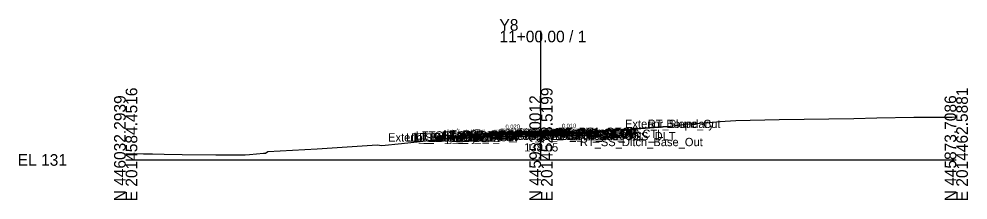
# Model space of a CAD drawing. Extents: x -26 to 1403, y -10 to 8043.
# Drawn here: x -25.7 to 202.8, y 1990.3 to 2034.1 of the extents above; entities that cross this region are included whole.
import ezdxf

# ---------------------------------------------------------------- set-up
doc = ezdxf.new("R2010")
doc.units = 0
for name, color, linetype in [('Default', 7, 'Continuous'), ('Exist CMT Pavement', 7, 'Continuous'), ('Exist Cross Section Cell', 7, 'Continuous'), ('Exist XS Center Line Elevation Label', 7, 'Continuous'), ('Exist XS Ground Line', 7, 'Continuous'), ('Prop CMT Pvmt Course 1', 7, 'Continuous'), ('Prop CMT Pvmt Course 2', 7, 'Continuous'), ('Prop CMT Pvmt Course 3', 7, 'Continuous'), ('Prop CMT Pvmt Surface', 7, 'Continuous'), ('Prop CMT Pvmt Surface Shoulder', 7, 'Continuous'), ('Prop CMT Shld Paved Course 1', 7, 'Continuous'), ('Prop CMT Shld Paved Course 2', 7, 'Continuous'), ('Prop CMT Shld Paved Course 3', 7, 'Continuous'), ('Prop CMT Slope Grass', 7, 'Continuous'), ('Prop CMT Subgrade Earthwork', 7, 'Continuous'), ('Prop XS Earthwork Shape', 7, 'Continuous'), ('Prop XS SE Text', 7, 'Continuous'), ('Prop XS Side Slope Text', 7, 'Continuous'), ('Scratch_Level_0', 7, 'Continuous')]:
    doc.layers.add(name, color=color, linetype=linetype)

msp = doc.modelspace()

# ---------------------------------------------------------------- linework, layer by layer
at = {"layer": 'Exist CMT Pavement'}
msp.add_lwpolyline([(88.73, 2006.68), (89.55, 2006.69), (99.48, 2007.03), (100, 2007.05), (100.46, 2007.07), (101.34, 2007.05), (111.48, 2006.77)], dxfattribs=at)
at = {"layer": 'Exist Cross Section Cell'}
for p, q in [((100, 2000), (100, 2031.22)), ((0, 2000), (100, 2000)), ((100, 2000), (200, 2000))]:
    msp.add_line(p, q, dxfattribs=at)
at = {"layer": 'Exist XS Ground Line'}
msp.add_lwpolyline([(0, 2001.54), (4.31, 2001.49), (6.46, 2001.47), (9.25, 2001.41), (13.59, 2001.31), (21.74, 2001.23), (28.74, 2001.22), (29.85, 2001.3), (33.17, 2001.63), (33.66, 2001.66), (34.23, 2002.08), (46.13, 2002.7), (60.54, 2003.65), (61.7, 2003.51), (66.38, 2004.01), (70.9, 2004.47), (83.32, 2005.96), (83.87, 2006.09), (88.73, 2006.68), (89.55, 2006.69), (99.48, 2007.03), (100, 2007.05), (100.46, 2007.07), (101.34, 2007.05), (111.48, 2006.77), (113.38, 2006.92), (118.89, 2007.28), (130.44, 2008.1), (134.84, 2008.61), (140.56, 2009.07), (143.05, 2009.26), (146.92, 2009.52), (157.35, 2009.8), (175.34, 2010.05), (180.89, 2010.18), (189.8, 2010.32), (193.51, 2010.33), (199.03, 2010.33), (200, 2010.41)], dxfattribs=at)
at = {"layer": 'Prop CMT Pvmt Course 1'}
for points in [[(100, 2006.68), (86.49, 2006.41)], [(100, 2006.68), (113.35, 2006.81)], [(100, 2006.43), (100, 2006.68)], [(100, 2006.43), (100, 2006.68)], [(113.35, 2006.56), (100, 2006.43)], [(113.35, 2006.81), (113.35, 2006.56)], [(86.49, 2006.16), (100, 2006.43)], [(86.49, 2006.41), (86.49, 2006.16)]]:
    msp.add_lwpolyline(points, dxfattribs=at)
msp.add_lwpolyline([(100, 2006.43), (100, 2006.56), (100, 2006.56), (100, 2006.43)], close=True, dxfattribs=at)
msp.add_lwpolyline([(100, 2006.43), (100, 2006.56), (100, 2006.56), (100, 2006.43)], close=True, dxfattribs=at)
at = {"layer": 'Prop CMT Pvmt Course 2'}
for points in [[(100, 2006.43), (113.35, 2006.56)], [(113.35, 2006.56), (113.35, 2006.31)], [(100, 2006.43), (86.49, 2006.16)], [(86.49, 2005.91), (100, 2006.18)], [(86.49, 2006.16), (86.49, 2005.91)], [(100, 2006.18), (100, 2006.43)], [(100, 2006.18), (100, 2006.43)], [(113.35, 2006.31), (100, 2006.18)]]:
    msp.add_lwpolyline(points, dxfattribs=at)
at = {"layer": 'Prop CMT Pvmt Course 3'}
for points in [[(100, 2006.18), (86.49, 2005.91)], [(86.49, 2005.91), (86.49, 2005.54)], [(86.49, 2005.54), (100, 2005.81)], [(100, 2006.18), (113.35, 2006.31)], [(100, 2005.81), (100, 2006.18)], [(100, 2005.81), (100, 2006.18)], [(113.35, 2005.94), (100, 2005.81)], [(113.35, 2006.31), (113.35, 2005.94)]]:
    msp.add_lwpolyline(points, dxfattribs=at)
at = {"layer": 'Prop CMT Pvmt Surface'}
for points in [[(100, 2006.68), (86.49, 2006.41)], [(100, 2006.68), (113.35, 2006.81)]]:
    msp.add_lwpolyline(points, dxfattribs=at)
at = {"layer": 'Prop CMT Pvmt Surface Shoulder'}
for points in [[(113.35, 2006.81), (113.35, 2006.81)], [(86.49, 2006.41), (86.49, 2006.41)]]:
    msp.add_lwpolyline(points, dxfattribs=at)
at = {"layer": 'Prop CMT Shld Paved Course 1'}
for points in [[(113.35, 2006.81), (113.35, 2006.81)], [(113.35, 2006.81), (113.6, 2006.56)], [(113.35, 2006.56), (113.35, 2006.81)], [(113.6, 2006.56), (113.35, 2006.56)], [(86.49, 2006.41), (86.24, 2006.16)], [(86.24, 2006.16), (86.49, 2006.16)], [(86.49, 2006.41), (86.49, 2006.41)], [(86.49, 2006.16), (86.49, 2006.41)]]:
    msp.add_lwpolyline(points, dxfattribs=at)
at = {"layer": 'Prop CMT Shld Paved Course 2'}
for points in [[(113.35, 2006.56), (113.6, 2006.56), (113.86, 2006.3)], [(113.35, 2006.31), (113.35, 2006.56)], [(86.49, 2006.16), (86.24, 2006.16), (85.98, 2005.9)], [(85.98, 2005.9), (86.49, 2005.91)], [(86.49, 2005.91), (86.49, 2006.16)], [(113.86, 2006.3), (113.35, 2006.31)]]:
    msp.add_lwpolyline(points, dxfattribs=at)
at = {"layer": 'Prop CMT Shld Paved Course 3'}
for points in [[(85.1, 2005.51), (86.49, 2005.54)], [(86.49, 2005.91), (85.98, 2005.9), (85.6, 2005.52)], [(86.49, 2005.54), (86.49, 2005.91)], [(113.35, 2005.94), (113.35, 2006.31)], [(113.35, 2006.31), (113.86, 2006.3), (114.24, 2005.92)], [(114.74, 2005.91), (113.35, 2005.94)]]:
    msp.add_lwpolyline(points, dxfattribs=at)
at = {"layer": 'Prop CMT Slope Grass'}
msp.add_line((113.35, 2006.81), (130.44, 2008.1), dxfattribs=at)
msp.add_lwpolyline([(86.49, 2006.41), (80.49, 2005.93), (79.05, 2005.45)], dxfattribs=at)
at = {"layer": 'Prop CMT Subgrade Earthwork'}
for p, q in [((115.83, 2007), (114.74, 2005.91)), ((85.1, 2005.51), (79.05, 2005.45))]:
    msp.add_line(p, q, dxfattribs=at)
for points in [[(86.49, 2005.54), (85.1, 2005.51)], [(100, 2005.81), (86.49, 2005.54)], [(100, 2005.81), (113.35, 2005.94)], [(113.35, 2005.94), (114.74, 2005.91)]]:
    msp.add_lwpolyline(points, dxfattribs=at)
at = {"layer": 'Prop XS Earthwork Shape'}
for points in [[(118.89, 2007.28), (130.44, 2008.1), (115.83, 2007), (114.74, 2005.91), (113.35, 2005.94), (100, 2005.81), (86.49, 2005.54), (85.1, 2005.51), (79.05, 2005.45), (83.32, 2005.96), (83.87, 2006.09), (86.46, 2006.41), (86.49, 2006.41), (100, 2006.68), (110.91, 2006.79), (111.48, 2006.77), (111.8, 2006.8), (113.38, 2006.92)], [(100.46, 2007.07), (101.34, 2007.05), (110.91, 2006.79), (100, 2006.68), (86.49, 2006.41), (86.46, 2006.41), (88.73, 2006.68), (89.55, 2006.69), (99.48, 2007.03), (100, 2007.05)], [(111.48, 2006.77), (111.8, 2006.8), (110.91, 2006.79)]]:
    msp.add_lwpolyline(points, close=True, dxfattribs=at)

# ---------------------------------------------------------------- texts
at = {"layer": 'Default'}
msp.add_text('-', height=0.0001, dxfattribs=at).set_placement((0, 2000))
at = {"layer": 'Exist Cross Section Cell'}
for s, p in [('Y8', (90, 2031.22)), ('11+00.00 / 1', (90, 2028.42)), ('EL 131', (-26, 1998.6))]:
    msp.add_text(s, height=2.8, dxfattribs=at).set_placement(p)
for s, p in [('E 2014584.4516', (2.8, 1990)), ('E 2014523.5199', (102.8, 1990)), ('E 2014462.5881', (202.8, 1990)), ('N 446032.2939', (0, 1990)), ('N 445953.0012', (100, 1990)), ('N 445873.7086', (200, 1990))]:
    msp.add_text(s, height=2.8, rotation=90, dxfattribs=at).set_placement(p)
at = {"layer": 'Exist XS Center Line Elevation Label'}
msp.add_text('138.05', height=2, dxfattribs=at).set_placement((95.98, 2002.05))
at = {"layer": 'Prop XS SE Text'}
for s, rotation, p in [('0.020', 1.1458, (91.48, 2007.51)), ('0.010', 0.5729, (105.03, 2007.73))]:
    msp.add_text(s, height=1, rotation=rotation, dxfattribs=at).set_placement(p)
at = {"layer": 'Prop XS Side Slope Text'}
msp.add_text('3:1', height=1, rotation=18.4332, dxfattribs=at).set_placement((78.78, 2006.15))
at = {"layer": 'Scratch_Level_0'}
for s, p in [('Exterior Boundary', (120.24, 2007.71)), ('RT_Slope_Cut', (125.69, 2007.71)), ('Exterior Boundary', (63.19, 2004.45)), ('LT_Slope_Cut', (68.69, 2004.45)), ('LT_Sub_Trench_Out', (69.31, 2004.51)), ('LT_Slope_Fill', (69.57, 2004.45)), ('LT_GS_OS_CTL', (69.86, 2004.93)), ('LT_PS3_Shelf_Out', (71.47, 2004.89)), ('LT_PS3_OEOP', (76.22, 2004.9)), ('LT_PS2_OEOP', (76.47, 2005.16)), ('LT_Sub_OEOT', (76.57, 2004.54)), ('LT_PV2_OEOT', (76.67, 2005.16)), ('LT_PV3_OEOT', (76.67, 2004.91)), ('LT_PV1_OEOT', (77.23, 2005.41)), ('LT_PS1_OEOP', (77.3, 2005.41)), ('RT_Sub_OEEOP', (89.17, 2004.81)), ('LT_Sub_OEEOP', (89.21, 2004.81)), ('RT_PV2_OEEOP', (89.26, 2005.43)), ('RT_PV3_OEEOP', (89.26, 2005.18)), ('LT_PV2_OEEOP', (89.31, 2005.43)), ('LT_PV3_OEEOP', (89.31, 2005.18)), ('RT_PV1_OEEOP', (89.83, 2005.56)), ('LT_PV1_OEEOP', (89.87, 2005.56)), ('RT_PV2_IEEOP', (89.91, 2005.43)), ('LT_PV2_IEEOP', (89.95, 2005.43)), ('RT_PV1_IEEOP', (90.47, 2005.56)), ('LT_PV1_IEEOP', (90.52, 2005.56)), ('PV2_PGL', (93.91, 2005.43)), ('PV1_PGL', (94.47, 2005.68)), ('RT_Sub_Trench_Out', (98.9, 2004.91)), ('RT_PS3_Shelf_Out', (100.3, 2005.29)), ('RT_Sub_OEOT', (103.38, 2004.94)), ('RT_PV2_OEOT', (103.47, 2005.56)), ('RT_PV3_OEOT', (103.47, 2005.31)), ('RT_PS2_OEOP', (103.79, 2005.56)), ('RT_PV1_OEOT', (104.04, 2005.81)), ('RT_PS3_OEOP', (104.05, 2005.3)), ('RT_PS1_OEOP', (104.1, 2005.81)), ('RT_GS_OS_CTL', (108.67, 2005.33)), ('RT_Sub_OSS_DLT', (108.94, 2004.77)), ('LT_Sub_OSS_DLT', (67.51, 2004.41)), ('RT_SS_Ditch_Base_Out', (109.38, 2003.33))]:
    msp.add_text(s, height=2, dxfattribs=at).set_placement(p)

doc.saveas('drawing.dxf')
